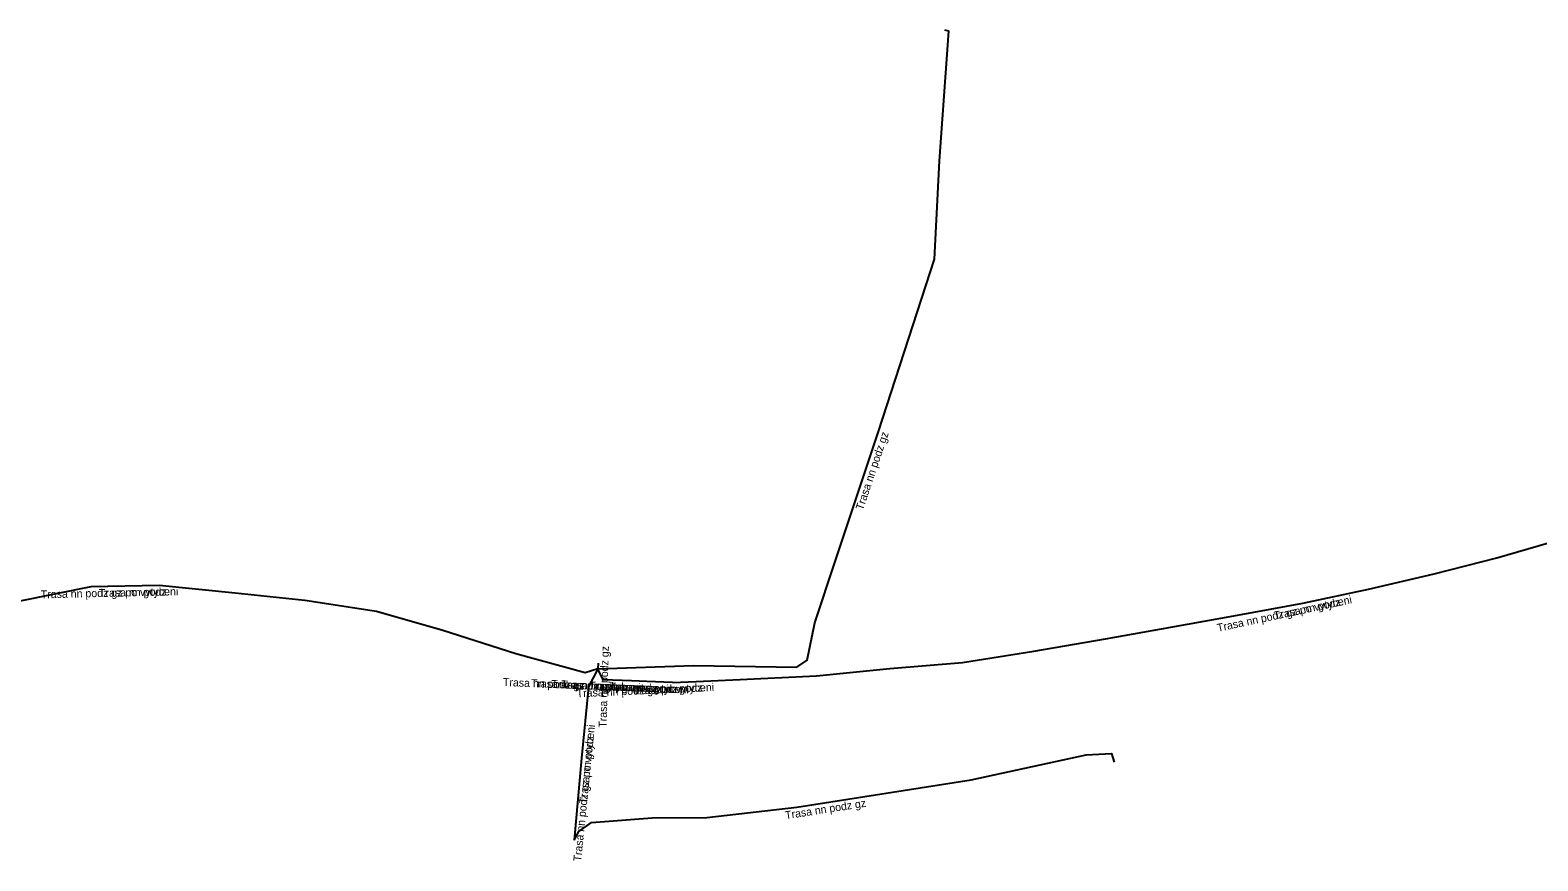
# Model space of a CAD drawing. Extents: x -817778 to -817398, y -1067927 to -1067625.
# Drawn here: x -817588.3 to -817493, y -1067821.4 to -1067768.8 of the extents above; entities that cross this region are included whole.
import ezdxf

# ---------------------------------------------------------------- set-up
doc = ezdxf.new("R2010")
doc.units = 0
doc.layers.add('Popiskový text - Ostatní atributy Trasy', color=7, linetype='Continuous')
doc.layers.add('Spojnice NN', color=7, linetype='Continuous')

msp = doc.modelspace()

# ---------------------------------------------------------------- linework, layer by layer
at = {"layer": 'Spojnice NN'}
for points in [[(-817552.43, -1067809.23), (-817546.38, -1067809.04), (-817539.86, -1067809.13), (-817539.2, -1067808.7), (-817538.72, -1067806.34), (-817537.41, -1067802.38), (-817534.68, -1067794.22), (-817531.14, -1067783.33), (-817530.83, -1067777.11), (-817530.24, -1067768.9), (-817530.5, -1067768.84)], [(-817546.215, -1067810.04), (-817543.44, -1067809.91), (-817538.61, -1067809.68), (-817533.97, -1067809.22), (-817529.37, -1067808.83), (-817524.86, -1067808.13), (-817520.32, -1067807.35), (-817516.2, -1067806.6), (-817511.99, -1067805.84), (-817507.85, -1067805.09), (-817503.69, -1067804.2), (-817499.55, -1067803.24), (-817495.57, -1067802.22), (-817491.66, -1067801.09), (-817487.75, -1067799.96), (-817483.74, -1067798.69), (-817479.63, -1067797.39), (-817475.88, -1067795.84), (-817472.2, -1067794.06), (-817470.4, -1067792.92), (-817469.52, -1067791.58)], [(-817546.215, -1067810.04), (-817543.44, -1067809.91), (-817538.61, -1067809.68), (-817533.97, -1067809.22), (-817529.37, -1067808.83), (-817524.86, -1067808.13), (-817520.32, -1067807.35), (-817516.2, -1067806.6), (-817511.99, -1067805.84), (-817507.85, -1067805.09), (-817503.69, -1067804.2), (-817499.55, -1067803.24), (-817495.57, -1067802.22), (-817491.66, -1067801.09), (-817487.75, -1067799.96), (-817483.74, -1067798.69), (-817479.63, -1067797.39), (-817475.88, -1067795.84), (-817472.2, -1067794.06), (-817470.4, -1067792.92), (-817469.52, -1067791.58)], [(-817552.43, -1067809.23), (-817553.23, -1067809.5), (-817557.63, -1067808.3), (-817562.23, -1067806.82), (-817566.44, -1067805.62), (-817570.96, -1067804.92), (-817575.37, -1067804.46), (-817580.18, -1067803.96), (-817584.51, -1067804.06), (-817589, -1067804.97), (-817593.13, -1067805.75), (-817594.22, -1067806.17), (-817594.86, -1067806.67), (-817595.28, -1067807.3), (-817595.46, -1067808.44), (-817596.15, -1067812.8), (-817597.27, -1067817.36), (-817597.87, -1067820.99)], [(-817552.43, -1067809.23), (-817553.23, -1067809.5), (-817557.63, -1067808.3), (-817562.23, -1067806.82), (-817566.44, -1067805.62), (-817570.96, -1067804.92), (-817575.37, -1067804.46), (-817580.18, -1067803.96), (-817584.51, -1067804.06), (-817589, -1067804.97), (-817593.13, -1067805.75), (-817594.22, -1067806.17), (-817594.86, -1067806.67), (-817595.28, -1067807.3), (-817595.46, -1067808.44), (-817596.15, -1067812.8), (-817597.27, -1067817.36), (-817597.87, -1067820.99)], [(-817552.42, -1067808.89), (-817552.43, -1067809.23)], [(-817552.43, -1067809.23), (-817553.02, -1067810.38), (-817553.48, -1067814.89), (-817553.93, -1067820.08)], [(-817552.43, -1067809.23), (-817553.02, -1067810.38), (-817553.48, -1067814.89), (-817553.93, -1067820.08)], [(-817550.303, -1067810.004), (-817552.11, -1067809.93), (-817552.43, -1067809.23)], [(-817550.303, -1067810.004), (-817552.11, -1067809.93), (-817552.43, -1067809.23)], [(-817549.345, -1067810.043), (-817550.303, -1067810.004)], [(-817549.345, -1067810.043), (-817550.303, -1067810.004)], [(-817547.72, -1067810.11), (-817549.345, -1067810.043)], [(-817547.72, -1067810.11), (-817549.345, -1067810.043)], [(-817547.72, -1067810.11), (-817546.215, -1067810.04)], [(-817547.72, -1067810.11), (-817546.215, -1067810.04)], [(-817553.93, -1067820.08), (-817553.63, -1067819.54), (-817552.84, -1067818.96), (-817549, -1067818.67), (-817545.54, -1067818.64), (-817539.85, -1067817.99), (-817528.82, -1067816.27), (-817521.55, -1067814.67), (-817519.94, -1067814.59), (-817519.78, -1067815.15)]]:
    msp.add_lwpolyline(points, dxfattribs=at)

# ---------------------------------------------------------------- texts
at = {"layer": 'Popiskový text - Ostatní atributy Trasy'}
for s, rotation, p in [('Trasa nn podz gz', 71.50188, (-817535.674, -1067799.242)), ('Trasa nn podz gz po vytyceni', 1.32299, (-817587.664, -1067804.783)), ('Trasa nn podz', 1.32299, (-817583.98, -1067804.698)), ('Trasa nn podz gz po vytyceni', 12.07594, (-817513.216, -1067806.903)), ('Trasa nn podz', 12.07594, (-817509.613, -1067806.132)), ('Trasa nn podz gz', 88.31532, (-817551.89, -1067812.971)), ('Trasa nn podz gz po vytyceni', 357.6505, (-817558.445, -1067810.321)), ('Trasa nn podz gz po vytyceni', 357.65059, (-817556.678, -1067810.393)), ('Trasa nn podz gz po vytyceni', 357.65246, (-817555.386, -1067810.446)), ('Trasa nn podz', 357.6505, (-817554.763, -1067810.472)), ('Trasa nn podz gz po vytyceni', 2.67476, (-817553.763, -1067811.043)), ('Trasa nn podz', 357.65059, (-817552.996, -1067810.544)), ('Trasa nn podz', 357.65246, (-817551.704, -1067810.597)), ('Trasa nn podz', 2.67476, (-817550.082, -1067810.871)), ('Trasa nn podz gz po vytyceni', 84.17622, (-817553.496, -1067821.447)), ('Trasa nn podz', 84.17622, (-817553.122, -1067817.781)), ('Trasa nn podz gz', 8.86323, (-817540.551, -1067818.757))]:
    msp.add_text(s, height=0.5, rotation=rotation, dxfattribs=at).set_placement(p)

doc.saveas('drawing.dxf')
